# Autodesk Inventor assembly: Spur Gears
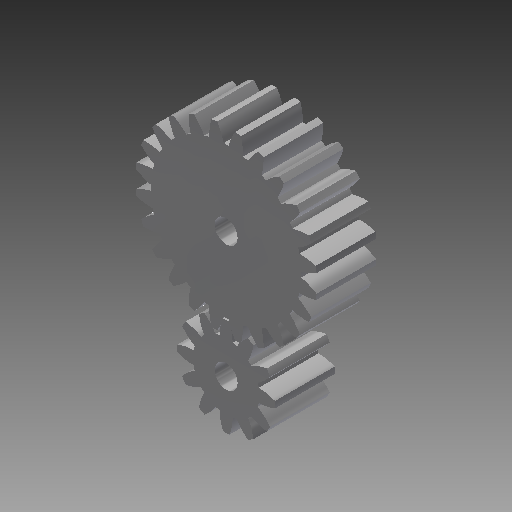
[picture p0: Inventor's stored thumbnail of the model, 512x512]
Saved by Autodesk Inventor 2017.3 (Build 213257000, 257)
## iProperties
Created: 2020-03
Part Number: Spur Gears
Document SubType Name: Assembly
Designer: Tim_G
Categories: <?xml version="1.0" encoding="UTF-16"?> <MemberInstance><Categories><FamilyTemplate/><ParamToTemplateMap><ParamToTemplate><ParamToTemplate CategoryParameter="//
ClientObjectVersion: 1
Author: Tim_G
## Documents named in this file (3)
- C:\Users\Tim_G\OneDrive - McMaster University\Documents\Documents\Books\McMaster First Year Courses\Winter Engineering 1C03\Project\Project Files (Prosthetic Frame Assembly)\Hand Assembly\Design Accelerator\Spur Gears2.iam
- C:\Users\Tim_G\OneDrive - McMaster University\Documents\Documents\Books\McMaster First Year Courses\Winter Engineering 1C03\Project\Project Files (Prosthetic Frame Assembly)\Hand Assembly\Design Accelerator\Spur Gear12.ipt
- C:\Users\Tim_G\OneDrive - McMaster University\Documents\Documents\Books\McMaster First Year Courses\Winter Engineering 1C03\Project\Project Files (Prosthetic Frame Assembly)\Hand Assembly\Design Accelerator\Spur Gear22.ipt
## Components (2 placed, 2 different names)
1. Spur Gear1:1 — Rotation:1
2. Spur Gear2:1 — Rotation:1
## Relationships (1: RelateRotation 1)
- Rotation:1 [RelateRotation]: Spur Gear1:1 ↔ Spur Gear2:1
